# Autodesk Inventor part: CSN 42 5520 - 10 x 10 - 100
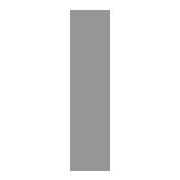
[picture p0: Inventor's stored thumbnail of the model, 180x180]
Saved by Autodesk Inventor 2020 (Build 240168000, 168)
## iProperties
Created: 2019-01
Part Number: CSN 42 5520 - 10 x 10 - 100
Material: Ocel, měkká
Description: Tyč
Document SubType Name: Modeling
Standard: CSN 42 5520
Designer: doma
Standards Organization: CSN
Language: cs-CZ
Size Designation: 10 x 10 - 100
Categories: <MemberInstance><Categories><Category DisplayName="Konstrukční profily" InternalName="089c4875-fa83-4c05-b084-43b9cc11f5ed" Mnemonic="GRDR"><CategoryParameter D
Stock Number: 10 x 10
Density: 7.85 g/cm^3
Appearance: Pololeštěná
Mass: 78.5 g
Surface Area: 42 cm^2
Volume: 10 cm^3
IsCustomPart: 1
G_L: 100,000 mm
Author: doma
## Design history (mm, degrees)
node "Počáteční rovina"
node "Koncová rovina"
sketch "Náčrt"
  geometry: L1 (5, -5)-(-5, -5); L2 (-5, -5)-(-5, 5); L3 (-5, 5)-(5, 5); L4 (5, 5)-(5, -5); L5 (-6, 0)-(8, 0); L6 (0, -30)-(0, 40); L7 (0, 54)-(0, -44) reference; L8 (-9.2, 0)-(13.2, 0) reference
  constraints: 12 end point, 2 collinear, 2 parallel, 1 horizontal, 1 perpendicular
  dimensions: "d0" = 10 distance between parallel lines of L3 L1 (= G_W); "d1" = 10 distance between parallel lines of L4 L2 (= G_H); "d4" = 5 distance between parallel lines of L6 L4 (= 0.5 x d1); "d5" = 5 distance between parallel lines of L5 L3 (= 0.5 x d0)
extrude "Těleso" new body sketch "Náčrt" stored distance "d2" = 100 (= G_L); taper "d3" = 0 deg
node "Driven Length"
  sketch "Sketch3"
    geometry: L1 (0, 0)-(10, 0) reference
    constraints: 2 end point, 1 horizontal
  workplane "Work Plane3"
  sketch "Sketch4"
    geometry: L1 (-2, 0)-(12, 0) reference; L2 (-2, 100)-(12, 100) reference
    dimensions: "d9" = 100 distance between parallel lines of L1 L2 (derived)
chamfer "Zkosení1" distance "d10" = 2; stored, may be unused: second distance "d11" = 2, angle "d12" = 45 deg
body "Solid1"
other parameters: "G_W" = 10 [user parameter; used in 1 equation term], "G_H" = 10 [user parameter; used in 1 equation term], "G_L" = 100 (= d9) [user parameter; used in 1 equation term], "G_OFFSET_START" = 0 [user parameter; used in 1 equation term], "G_OFFSET_END" = 0 [user parameter; used in 1 equation term], "d6" = 0 (computed from G_OFFSET_START), "d8" = 90 deg
